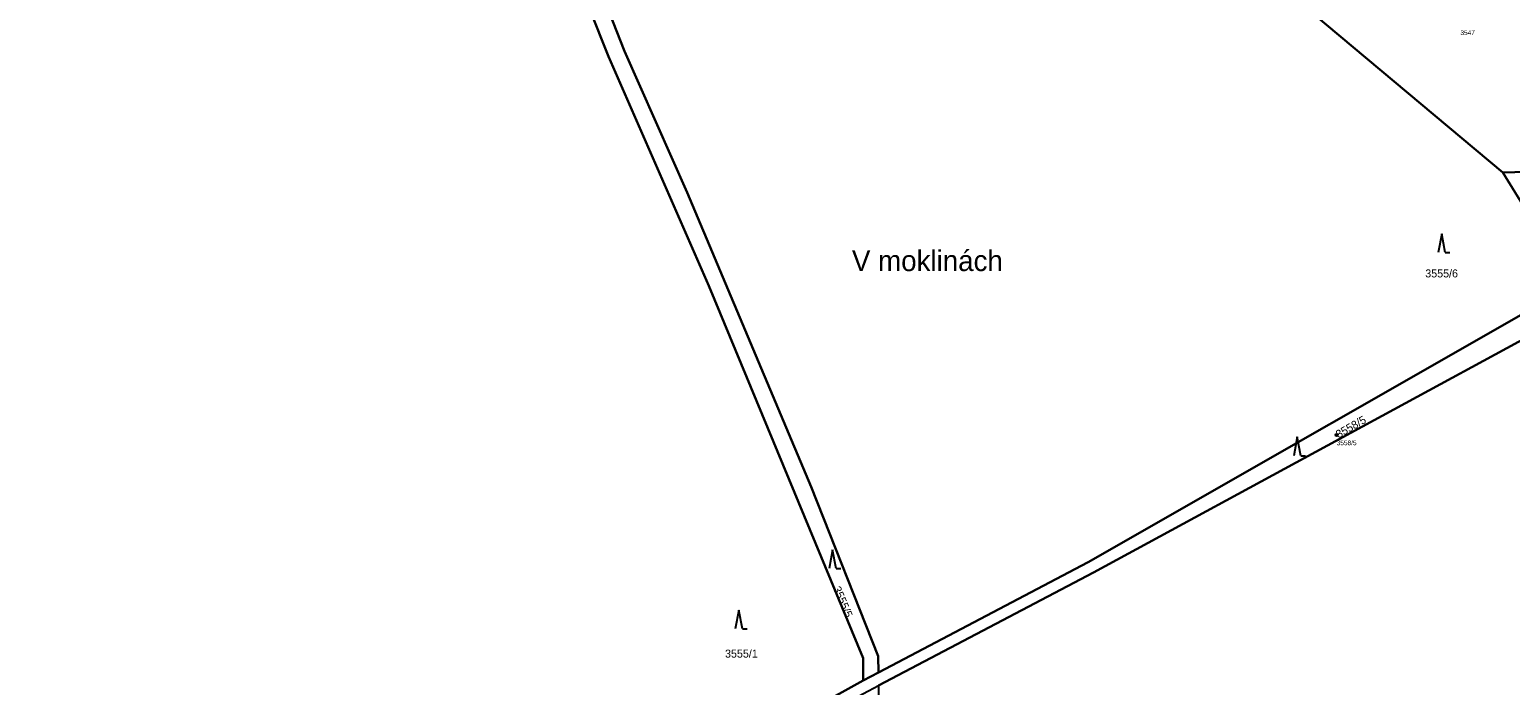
# Model space of a CAD drawing. Extents: x -761174 to -757114, y -1063806 to -1059397.
# Drawn here: x -758825.5 to -758511, y -1061272.3 to -1061133 of the extents above; entities that cross this region are included whole.
import ezdxf

# ---------------------------------------------------------------- set-up
doc = ezdxf.new("R2010")
doc.units = 0
for name, color, linetype in [('Definiční body', 7, 'Continuous'), ('Hranice parcel', 7, 'Continuous'), ('Parcelní čísla', 7, 'Continuous'), ('Polygon parcely', 7, 'Continuous'), ('Pop  PČ popisy', 7, 'Continuous'), ('Značky kultur', 7, 'Continuous')]:
    doc.layers.add(name, color=color, linetype=linetype)

msp = doc.modelspace()

# ---------------------------------------------------------------- linework, layer by layer
at = {"layer": 'Definiční body'}
msp.add_circle((-758547.86, -1061219.13), 0.25, dxfattribs=at)
at = {"layer": 'Hranice parcel'}
for p, q in [((-758553.04, -1061129.4), (-758512.58, -1061163.36)), ((-758481.77, -1061162.51), (-758512.58, -1061163.36)), ((-758512.58, -1061163.36), (-758497.81, -1061187.33)), ((-758648.42, -1061271.25), (-758645.19, -1061269.55))]:
    msp.add_line(p, q, dxfattribs=at)
for points in [[(-758648.42, -1061271.25), (-758648.45, -1061266.54), (-758681.23, -1061187.46), (-758702.48, -1061138.72), (-758722.83, -1061087.64), (-758723.08, -1061070.27), (-758731.25, -1061021.79), (-758748.87, -1060980.43), (-758771.03, -1060930.78), (-758785.41, -1060875.95), (-758825.45, -1060802.99)], [(-758645.19, -1061269.55), (-758645.26, -1061266.14), (-758659.46, -1061230.12), (-758685.77, -1061167.63), (-758699.11, -1061137.55), (-758719.07, -1061086.74), (-758719.33, -1061070.14), (-758728.14, -1061019.97), (-758768.31, -1060927.8), (-758782.04, -1060874.78), (-758822.23, -1060802.48)], [(-758645.19, -1061269.55), (-758600.64, -1061246.15), (-758497.81, -1061187.33)], [(-758645.14, -1061272.36), (-758599.48, -1061248.36), (-758495.19, -1061191.71)], [(-758753.89, -1061330.67), (-758718.22, -1061310.71), (-758678.82, -1061288.14), (-758648.42, -1061271.25)]]:
    msp.add_lwpolyline(points, dxfattribs=at)
at = {"layer": 'Polygon parcely'}
for points in [[(-758645.19, -1061269.55), (-758645.26, -1061266.14), (-758659.46, -1061230.12), (-758685.77, -1061167.63), (-758699.11, -1061137.55), (-758719.07, -1061086.74), (-758719.33, -1061070.14), (-758728.14, -1061019.97), (-758768.31, -1060927.8), (-758782.04, -1060874.78), (-758822.23, -1060802.48), (-758825.45, -1060802.99), (-758785.41, -1060875.95), (-758771.03, -1060930.78), (-758748.87, -1060980.43), (-758731.25, -1061021.79), (-758723.08, -1061070.27), (-758722.83, -1061087.64), (-758702.48, -1061138.72), (-758681.23, -1061187.46), (-758648.45, -1061266.54), (-758648.42, -1061271.25)], [(-758553.35, -1061097.44), (-758553.04, -1061129.4), (-758512.58, -1061163.36), (-758481.77, -1061162.51), (-758501.06, -1061138.11), (-758506.92, -1061106.3), (-758539.28, -1061094.33), (-758556.62, -1061071.82)], [(-758512.58, -1061163.36), (-758497.81, -1061187.33), (-758494.2, -1061187.97), (-758464.35, -1061181.81), (-758481.77, -1061162.51)], [(-758796.68, -1061357.59), (-758763.4, -1061338.87), (-758758.88, -1061336.33), (-758750.13, -1061331.44), (-758716.98, -1061312.88), (-758677.61, -1061290.32), (-758648.46, -1061274.14), (-758647.26, -1061273.47), (-758645.14, -1061272.36), (-758599.48, -1061248.36), (-758495.19, -1061191.71), (-758497.81, -1061187.33), (-758600.64, -1061246.15), (-758645.19, -1061269.55), (-758648.42, -1061271.25), (-758678.82, -1061288.14), (-758718.22, -1061310.71), (-758753.89, -1061330.67), (-758760.1, -1061334.15), (-758767.11, -1061338.09), (-758797.91, -1061355.41), (-758801.67, -1061356.34)]]:
    msp.add_lwpolyline(points, close=True, dxfattribs=at)
for points in [[(-758678.82, -1061288.14), (-758648.42, -1061271.25), (-758648.45, -1061266.54), (-758681.23, -1061187.46), (-758702.48, -1061138.72), (-758722.83, -1061087.64), (-758723.08, -1061070.27), (-758731.25, -1061021.79), (-758748.87, -1060980.43), (-758771.03, -1060930.78), (-758785.41, -1060875.95), (-758825.45, -1060802.99)], [(-758719.07, -1061086.74), (-758699.11, -1061137.55), (-758685.77, -1061167.63), (-758659.46, -1061230.12), (-758645.26, -1061266.14), (-758645.19, -1061269.55), (-758600.64, -1061246.15), (-758497.81, -1061187.33), (-758512.58, -1061163.36), (-758553.04, -1061129.4)], [(-758495.19, -1061191.71), (-758599.48, -1061248.36), (-758645.14, -1061272.36), (-758643.87, -1061353.41), (-758617.14, -1061358.84), (-758541.9, -1061357.01), (-758473.53, -1061355.69)]]:
    msp.add_lwpolyline(points, dxfattribs=at)
at = {"layer": 'Značky kultur'}
for p, q in [((-758525.55, -1061176.36), (-758526.3, -1061180.36)), ((-758524.8, -1061180.36), (-758525.55, -1061176.36)), ((-758524.8, -1061180.36), (-758523.8, -1061180.36)), ((-758556.24, -1061219.54), (-758556.99, -1061223.54)), ((-758555.49, -1061223.54), (-758556.24, -1061219.54)), ((-758555.49, -1061223.54), (-758554.49, -1061223.54)), ((-758654.91, -1061243.51), (-758655.66, -1061247.51)), ((-758654.16, -1061247.51), (-758654.91, -1061243.51)), ((-758654.16, -1061247.51), (-758653.16, -1061247.51)), ((-758674.83, -1061256.33), (-758675.58, -1061260.33)), ((-758674.08, -1061260.33), (-758674.83, -1061256.33)), ((-758674.08, -1061260.33), (-758673.08, -1061260.33))]:
    msp.add_line(p, q, dxfattribs=at)

# ---------------------------------------------------------------- texts
at = {"layer": 'Definiční body'}
for s, p in [('3547', (-758521.58, -1061134.14)), ('3558/5', (-758547.86, -1061221.29))]:
    msp.add_text(s, height=1, dxfattribs=at).set_placement(p)
at = {"layer": 'Parcelní čísla'}
for s, p in [('3555/6', (-758529.05, -1061185.64)), ('3555/1', (-758677.76, -1061266.42))]:
    msp.add_text(s, height=1.7, dxfattribs=at).set_placement(p)
for s, rotation, p in [('3558/5', 30, (-758547.43, -1061219.87)), ('3555/5', 293, (-758654.86, -1061251.7))]:
    msp.add_text(s, height=1.7, rotation=rotation, dxfattribs=at).set_placement(p)
at = {"layer": 'Pop  PČ popisy'}
msp.add_text('V moklinách', height=4.4, dxfattribs=at).set_placement((-758650.81, -1061184.29))

doc.saveas('drawing.dxf')
